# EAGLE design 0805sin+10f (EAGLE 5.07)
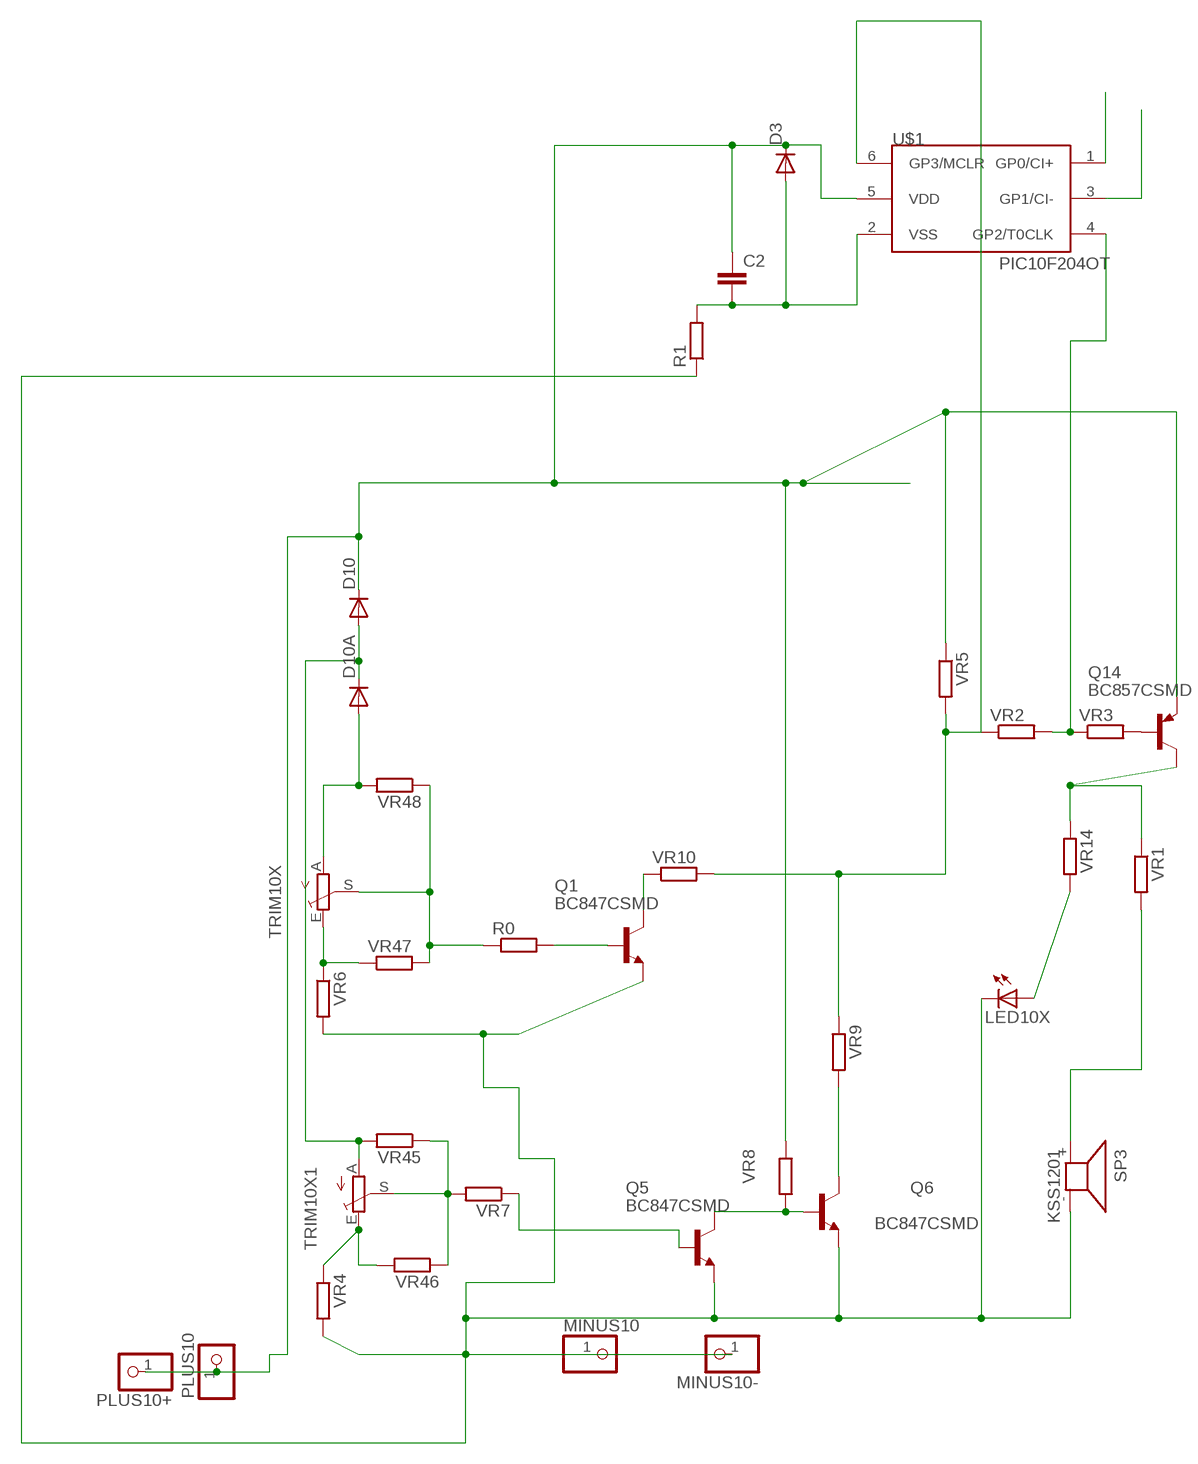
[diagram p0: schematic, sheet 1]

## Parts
C2  C-EUC0805  [C0805]
D3  DIODE-MINIMELF  [MINIMELF]
D10  DIODE-MINIMELF  [MINIMELF]
D10A  DIODE-MINIMELF  [MINIMELF]
LED10X  LEDCHIPLED_1206  [CHIPLED_1206]
MINUS10  PINHD-1X14.5MM  [1X4MM5]
MINUS10-  PINHD-1X11X0.4  [1X01]
PLUS10  PINHD-1X14.5MM  [1X4MM5]
PLUS10+  PINHD-1X11X0.4  [1X01]
Q1  BC847CSMD  [SOT23]
Q5  BC847CSMD  [SOT23]
Q6  BC847CSMD  [SOT23]
Q14  BC857CSMD  [SOT23-BEC]
R0  R-EU_R0805  [R0805]
R1  R-EU_R0805  [R0805]
SP3  KSS1201  KSS12017MM  [KSS1202]
TRIM10X  TRIM_EU-S64W  [S64W]
TRIM10X1  TRIM_EU-S64W  [S64W]
U$1  PIC10F204OT  [SOT23-6]
VR1  R-EU_R0805  [R0805]
VR2  R-EU_R0805  [R0805]
VR3  R-EU_R0805  [R0805]
VR4  R-EU_R1206  [R1206]
VR5  R-EU_R0805  [R0805]
VR6  R-EU_R1206  [R1206]
VR7  R-EU_M1206  [M1206]
VR8  R-EU_R1206  [R1206]
VR9  R-EU_R0805  [R0805]
VR10  R-EU_R0805  [R0805]
VR14  R-EU_R0805  [R0805]
VR45  R-EU_R0805  [R0805]
VR46  R-EU_R0805  [R0805]
VR47  R-EU_R0805  [R0805]
VR48  R-EU_R0805  [R0805]

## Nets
B: R0.1 TRIM10X.S VR47.2 VR48.1
B2: U$1.4(GP2/T0CLK) VR2.2 VR3.1
N$1: SP3.+ VR1.2
N$2: Q1.3(C) VR10.1
N$3: Q5.3(C) Q6.1(B) VR8.2
N$4: LED10X.A VR14.2
N$5: Q6.3(C) VR9.2
N$6: U$1.6(GP3/MCLR) VR2.1 VR5.2 VR9.1 VR10.2
N$7: Q1.1(B) R0.2
N$8: Q14.C VR1.1 VR14.1
N$10: Q14.B VR3.2
N$14: D10A.A TRIM10X.A VR48.2
N$17: D10.A D10A.C TRIM10X1.A VR45.2
N$22: TRIM10X1.S VR7.2 VR45.1 VR46.1
N$24: TRIM10X1.E VR4.1 VR46.2
N$128: TRIM10X.E VR6.1 VR47.1
N$138: U$1.1(GP0/CI+)
N$165: U$1.3(GP1/CI-)
N$168: Q5.1(B) VR7.1
PLUS11: C2.1 D3.C D10.C PLUS10+.1 PLUS10.1 Q14.E U$1.5(VDD) VR5.1 VR8.1
VSS: LED10X.C MINUS10-.1 MINUS10.1 Q1.2(E) Q5.2(E) Q6.2(E) R1.1 SP3.- VR4.2 VR6.2
VSS1: C2.2 D3.A R1.2 U$1.2(VSS)

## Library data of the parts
C2 = rcl:C-EU: CAPACITOR, European symbol
D3 D10 D10A = diode:DIODE-: DIODE
LED10X = led:LED: LED
MINUS10 MINUS10- PLUS10 PLUS10+ = pinhead:PINHD-1X1: PIN HEADER
Q1 Q5 Q6 = transistor-npn:BC847*: NPN Transistor
Q14 = transistor-pnp:BC857*: PNP Transistror
R0 R1 VR1-VR10 VR14 VR45-VR48 = rcl-2:R-EU_: RESISTOR, European symbol
SP3 = buzzer:KSS1201: SPEAKER
TRIM10X TRIM10X1 = pot:TRIM_EU-: POTENTIOMETER
U$1 = microchip-3:PIC10F2*: uPC nW 0,25/0,5k Program Flash memory Comparator

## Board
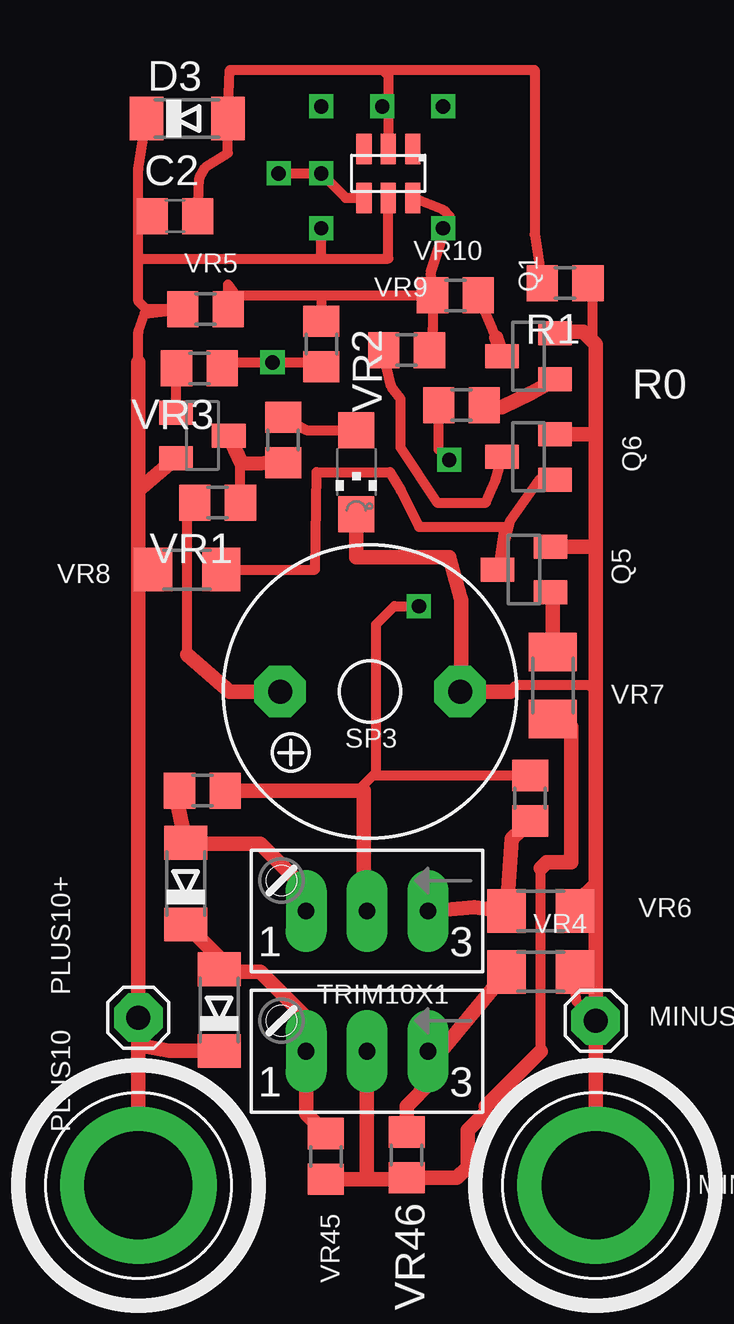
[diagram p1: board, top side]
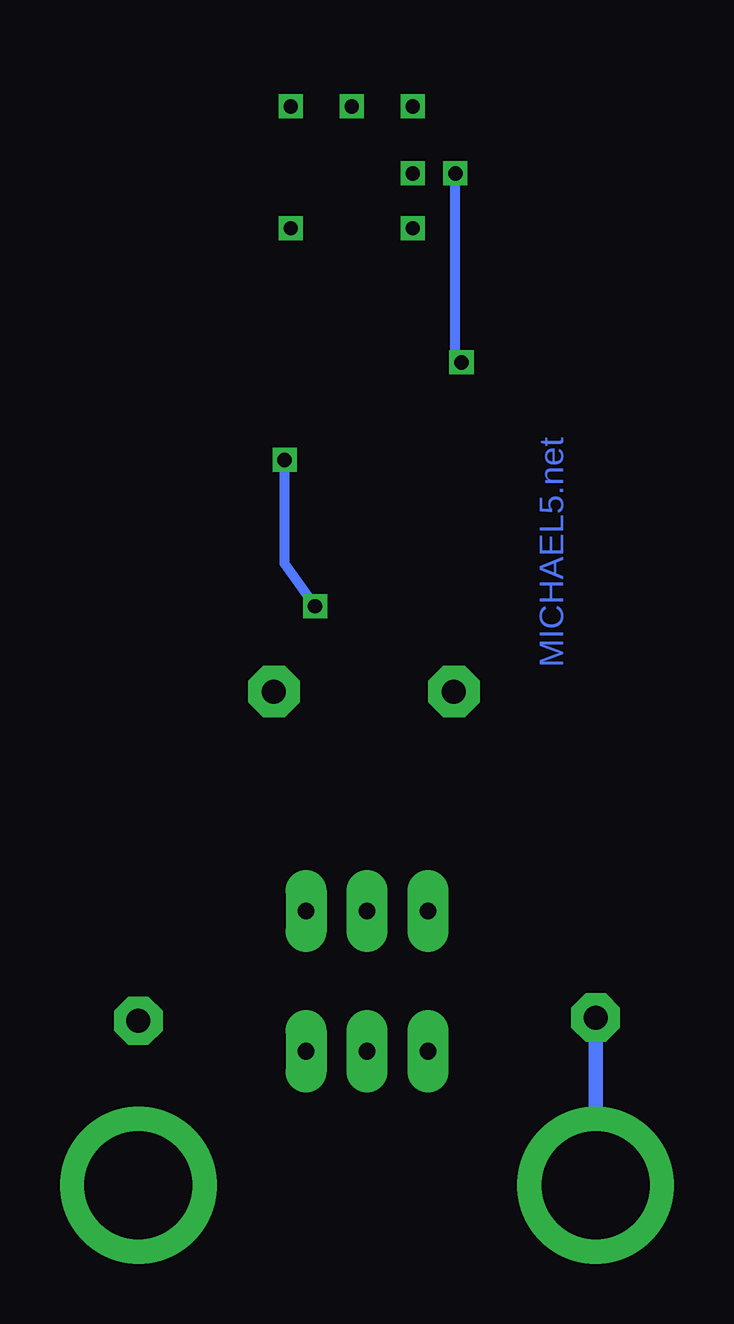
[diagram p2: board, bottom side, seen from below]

No outline drawn. Coordinates in mm, seen from the top.
Copper layers (1*16): Top 0.035mm / dielectric 1.5mm / Bottom 0.035mm
Design rules "default *": minimum track width 8mil, minimum drill 4mil, track to track 8mil, track to pad 8mil, pad to pad 8mil, via to via 8mil, smd to smd 8mil, copper to edge 40mil, drill to drill 8mil, minimum pad ring 20mil, minimum via ring 8mil, stop-mask expansion 4mil, vias tented up to drill 0mil, thermal gap 10mil

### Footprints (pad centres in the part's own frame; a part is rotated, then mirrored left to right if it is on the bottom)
C0805 = smd 1.3 x 1.5: 1 -0.95,0; 2 0.95,0
MINIMELF = smd 1.4 x 1.8: A 1.7,0; C -1.7,0
CHIPLED_1206 = smd 1.5 x 1.5: A 0,-1.75; C 0,1.75
1X4MM5 = drill 4.5 pad 6.35 round: 1 0,0
1X01 = drill 1 pad 1.676 octagon: 1 0,0
SOT23 = smd 1 x 1.4: 1 -0.95,-1.1; 2 0.95,-1.1; 3 0,1.1
SOT23-BEC = smd 1 x 1.4: B -0.95,-1.1; C 0,1.1; E 0.95,-1.1
R0805 = smd 1.3 x 1.5: 1 -0.95,0; 2 0.95,0
KSS1202 = drill 1 pad 2.159 octagon: + 3.75,0; - -3.75,0
S64W = drill 0.7 long: A 2.54,1.27; E -2.54,1.27; S 0,1.27
SOT23-6 = smd 0.635 x 1.27: 1 -1.016,-1.016; 2 0,-1.016; 3 1.016,-1.016; 4 1.016,1.016; 5 0,1.016; 6 -1.016,1.016
R1206 = smd 1.6 x 1.803: 1 -1.422,0; 2 1.422,0
M1206 = smd 1.6 x 2: 1 -1.4,0; 2 1.4,0

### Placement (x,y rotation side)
C2  72.64,49.28 0 top
D3  73.15,53.34 0 top
D10  74.49,16.19 90 top
D10A  73.09,21.46 90 top
LED10X  80.2,38.61 180 top
MINUS10  90.17,8.89 0 top
MINUS10-  90.17,15.75 0 top
PLUS10  71.12,8.89 0 top
PLUS10+  71.12,15.88 0 top
Q1  87.38,43.43 90 top
Q5  87.19,34.54 90 top
Q6  87.38,39.24 90 top
Q14  73.79,40.13 270 top
R0  84.58,41.4 0 top
R1  88.9,46.48 180 top
SP3  80.77,29.46 180 top
TRIM10X  80.64,21.59 180 top
TRIM10X1  80.64,15.75 180 top
U$1  81.53,51.05 180 top
VR1  74.42,37.34 180 top
VR2  78.74,43.94 270 top
VR3  73.66,42.93 180 top
VR4  87.88,17.78 0 top
VR5  73.91,45.4 0 top
VR6  87.88,20.32 0 top
VR7  88.39,29.72 270 top
VR8  73.15,34.54 0 top
VR9  82.3,43.69 180 top
VR10  84.33,45.97 180 top
VR14  77.15,39.94 90 top
VR45  78.93,10.1 90 top
VR46  82.3,10.16 90 top
VR47  87.44,25.02 90 top
VR48  73.79,25.34 180 top

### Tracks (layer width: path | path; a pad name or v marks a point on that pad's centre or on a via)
B  (via drill 0.6)
  Top 0.406: R0.1 83.63,39.56 v84.07,39.12 | v82.8,33.02 81.79,33.02 81.03,32.26 81.03,26.1 80.9,25.97 | 80.9,25.97 VR47.2 | 80.26,25.34 80.9,25.97
  Top 0.61: VR48.1 80.26,25.34 80.52,25.34 80.52,20.45 TRIM10X.S
  Bottom 0.406: v84.07,39.12 84.07,34.8 v82.8,33.02
B2  (via drill 0.6)
  Top 0.406: VR2.2 78.55,43.18 v76.71,43.18 74.86,43.18 VR3.1 | v76.96,51.05 v78.74,51.05 79.76,50.04 U$1.4
  Bottom 0.406: v76.71,43.18 76.96,43.43 v76.96,51.05
N$1
  Top 0.406: 73.15,30.99 73.15,37.02 VR1.2
  Top 0.61: SP3.+ 74.93,29.46 73.15,30.99
N$2
  Top 0.406: 86.04,44.2 VR10.1
  Top 0.61: Q1.3 86.04,44.2
N$3
  Top 0.406: VR8.2 78.49,34.54 78.55,38.61 81.6,38.61 82.04,37.85 82.8,36.32 86.36,36.32 Q5.3 86.11,34.56 86.61,36.58 87.82,38.29 Q6.1
N$4
  Top 0.406: LED10X.A 78.11,40.36 VR14.2
N$5
  Top 0.406: Q6.3 85.98,38.23 85.6,37.34 83.57,37.34 82.04,39.62 82.04,41.66 81.66,42.16 81.28,43.75 VR9.2
N$6
  Top 0.406: U$1.6 83.82,49.53 84.07,49.28 83.31,46.92 VR10.2 | VR10.2 83.38,44.57 VR9.1 | VR5.2 74.86,46.42 75.18,45.97 78.74,45.97 | 78.74,45.97 VR10.2 | 78.74,45.97 VR2.1
N$7
  Top 0.406: R0.2 86.26,41.3 | 88.41,42.42 Q1.1
  Top 0.61: 86.26,41.3 87.5,41.91 88.41,42.42
N$8
  Top 0.406: 75.42,38.96 75.37,38.96 VR1.1
  Top 0.61: VR14.1 75.42,38.96 Q14.C
N$9  (via drill 0.6)
  other vias: 83.82,48.77
N$10
  Top 0.406: Q14.B 72.69,42.9 VR3.2
N$11  (via drill 0.6)
  other vias: 83.82,53.85
N$12  (via drill 0.6)
  other vias: 81.28,53.85
N$13  (via drill 0.6)
  other vias: 78.74,53.85
N$14
  Top 0.61: TRIM10X.A 78.11,21.21 76.2,23.11 72.59,23.11 D10A.A 72.77,24.64 VR48.2
N$17
  Top 0.61: D10.A 74.69,17.89 | D10.A 74.6,17.78 76.2,17.78 78.11,15.88 TRIM10X1.A 78.11,11.87 VR45.2 | D10.A 74.49,18.37 D10A.C
N$22
  Top 0.406: 85.6,11.94 85.6,12.19 | 87.88,14.48 87.88,22.1 | 89.15,28.01 88.7,28.01 VR7.2 | 80.77,9.14 80.64,9.27 | VR45.1 | 82.23,9.14 VR46.1
  Top 0.61: VR46.1 84.39,9.21 84.84,9.65 84.84,11.18 85.6,11.94 | 85.6,12.19 87.88,14.48 | 87.88,22.1 88.14,22.35 89.15,22.35 89.15,28.01 | 80.64,9.27 TRIM10X1.S | VR45.1 80.77,9.14 82.23,9.14
N$24
  Top 0.406: 83.31,13.21 83.31,14.35 TRIM10X1.E
  Top 0.61: VR4.1 83.86,14.64 TRIM10X1.E | VR46.2 82.3,12.19 83.31,13.21
N$128
  Top 0.61: VR47.1 86.67,23.33 VR6.1 85.11,20.47 TRIM10X.E
N$168
  Top 0.406: 88.39,33.49 Q5.1
  Top 0.61: VR7.1 88.39,33.49
PLUS11  (via drill 0.6)
  Top 0.406: VR8.1 71.73,33.93 71.12,34.54 | 71.12,43.18 71.12,44.45 71.38,45.21 VR5.1 71.44,45.4 71.12,45.72 71.12,47.5 | 71.12,36.58 71.12,37.85 | U$1.5 81.53,47.5 78.74,47.5 | 78.74,47.5 v78.74,48.77 | 71.12,47.5 71.12,49.28 | 71.12,49.28 71.12,51.23 D3.C | 71.12,49.28 C2.1 | 71.12,47.5 78.74,47.5
  Top 0.61: 72.5,14.49 D10.C 72.4,14.49 71.12,14.73 | PLUS10.1 71.12,14.73 | 71.12,14.73 PLUS10+.1 71.12,34.54 71.12,36.58 71.12,43.18 | 71.12,37.85 Q14.E
  Bottom 0.61: PLUS10.1 PLUS10+.1
VSS
  Top 0.406: VR6.2 89.31,20.73 90.17,21.59 | 88.54,44.45 Q1.2 | 86.61,29.46 86.87,29.72 89.92,29.72 90.17,29.46 | 90.17,35.56 90.1,35.49 | 90.17,40.13 90.11,40.19 | SP3.- 84.58,29.82 | VR4.2 89.37,16.55 MINUS10-.1 | R1.1 90.04,46.29 90.04,44.07
  Top 0.61: MINUS10.1 MINUS10-.1 90.17,21.59 90.17,29.46 90.17,35.56 90.17,40.13 90.17,43.94 90.04,44.07 89.66,44.45 88.54,44.45 | 86.61,29.46 SP3.- | 90.1,35.49 Q5.2 | 90.11,40.19 Q6.2 | LED10X.C 80.2,35.05 84.07,35.05 84.58,33.27 84.58,29.82
VSS1
  Top 0.406: R1.2 87.63,48.51 87.63,55.37 81.28,55.37 | 81.28,55.37 74.93,55.37 D3.A 74.85,51.89 73.91,51.31 73.66,50.87 C2.2 | U$1.2 81.53,55.12 81.28,55.37

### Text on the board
Bottom: MICHAEL5.net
